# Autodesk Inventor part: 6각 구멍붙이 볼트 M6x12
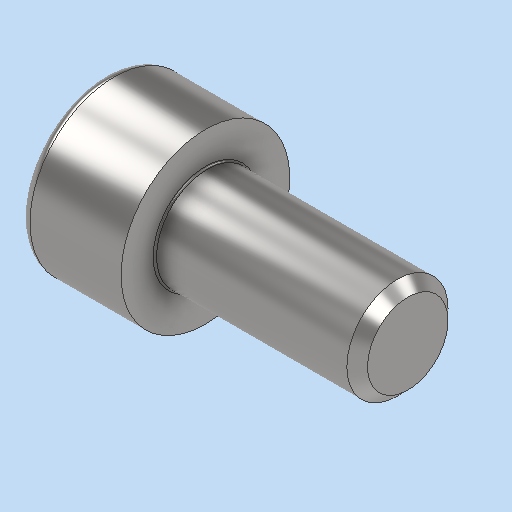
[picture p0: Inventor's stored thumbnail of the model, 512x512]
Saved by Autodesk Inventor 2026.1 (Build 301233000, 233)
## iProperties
Created: 2025-09
Part Number: 6각 구멍붙이 볼트 M6x12
Material: 강철, 연강
Description: 6각머리 태핑 나사
Document SubType Name: Modeling
Designer: PC-30
Density: 7.85 g/cm^3
Appearance: 기본값
Author: jhkim
Sending System: Autodesk Inventor 2026
Preprocessor: ST-DEVELOPER v20.1
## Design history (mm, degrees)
feature "Solid1"
node "솔리드1"
